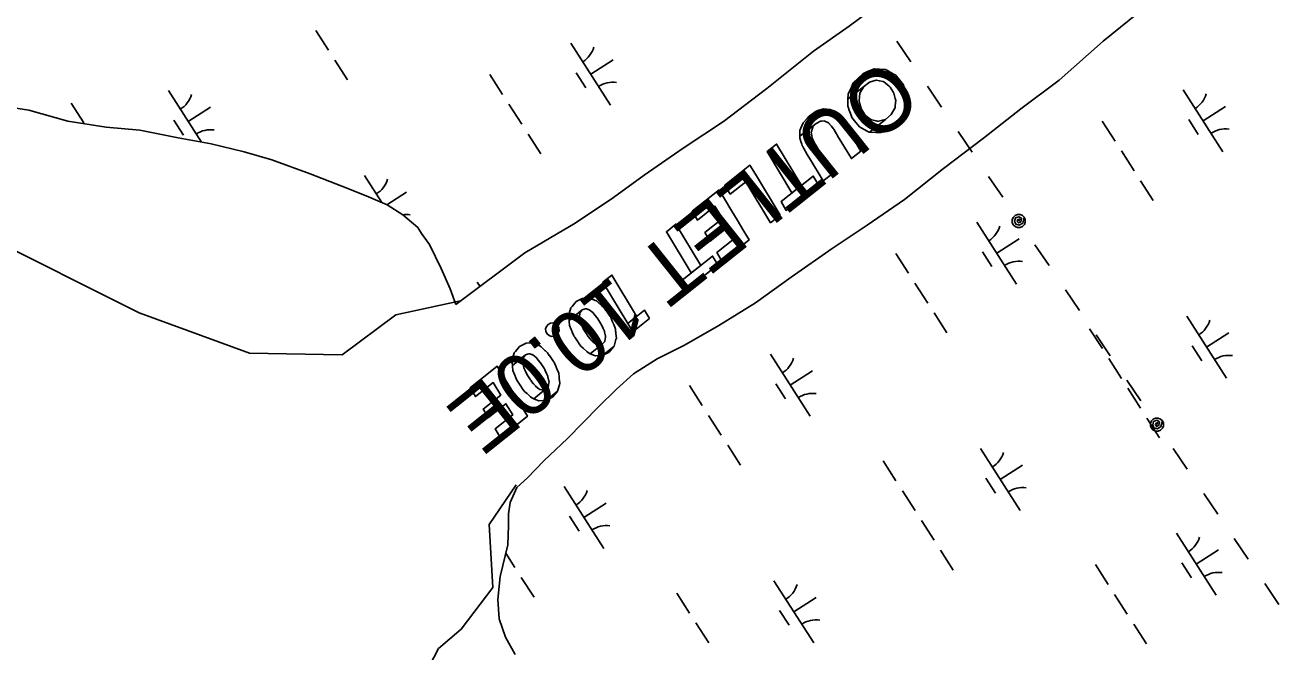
# Model space of a CAD drawing. Extents: x 3962991 to 3983549, y 181631 to 204078.
# Drawn here: x 3970044 to 3970895, y 197689 to 198115 of the extents above; entities that cross this region are included whole.
import ezdxf

# ---------------------------------------------------------------- set-up
doc = ezdxf.new("R2010")
doc.units = 0
for name, color, linetype in [('V-ANNO-MASK', 7, 'Continuous'), ('V-ANNO-MASK2', 7, 'Continuous'), ('V-RIVR-EDGE', 7, 'Continuous'), ('V-RIVR-IDEN', 7, 'Continuous'), ('V-UTIL-LINE', 7, 'Continuous'), ('V-WETL-SWMP', 7, 'Continuous')]:
    doc.layers.add(name, color=color, linetype=linetype)

msp = doc.modelspace()

# ---------------------------------------------------------------- linework, layer by layer
at = {"layer": 'V-ANNO-MASK2'}
for points in [[(3970615.3, 198082.74), (3970612.45, 198081.53), (3970605.99, 198075.33), (3970604.72, 198072.5), (3970602.58, 198067.74), (3970602.44, 198064.29), (3970612.94, 198072.65), (3970616.98, 198075.8), (3970621.62, 198077.12), (3970621.74, 198077.1), (3970623.79, 198076.73), (3970623.79, 198076.73), (3970626.39, 198076.27), (3970626.7, 198076.04), (3970627.97, 198075.06), (3970630.39, 198073.2), (3970630.55, 198072.96), (3970630.56, 198072.96), (3970630.95, 198072.36), (3970633.38, 198068.7), (3970633.39, 198068.71), (3970633.42, 198068.64), (3970633.5, 198068.36), (3970634.49, 198064.66), (3970634.83, 198063.4), (3970634.83, 198063.36), (3970634.49, 198059.88), (3970634.34, 198058.27), (3970634.33, 198058.2), (3970631.84, 198053.81), (3970631.83, 198053.78), (3970627.84, 198050.58), (3970616.92, 198041.89), (3970621.43, 198041.7), (3970624.67, 198041.56), (3970629.85, 198043.76), (3970632.17, 198044.75), (3970632.17, 198044.75), (3970638.43, 198050.6), (3970639.94, 198053.72), (3970642.08, 198058.14), (3970642.28, 198062.07), (3970642.28, 198062.11), (3970642.28, 198062.12), (3970642.41, 198064.63), (3970642.41, 198064.7), (3970642.49, 198066.24), (3970641.66, 198068.8), (3970641.66, 198068.83), (3970641.26, 198070.04), (3970640.1, 198073.61), (3970640.02, 198073.88), (3970639.99, 198073.96), (3970637.3, 198077.41), (3970636.86, 198077.98), (3970636.67, 198078.2), (3970634.85, 198080.54), (3970633.38, 198081.36), (3970633.03, 198081.55), (3970631.16, 198082.6), (3970629.68, 198083.42), (3970629.6, 198083.47), (3970627.84, 198084.44), (3970627.76, 198084.45), (3970623.81, 198084.64), (3970620.19, 198084.81)], [(3970612.88, 198072.53), (3970612.94, 198072.65), (3970602.44, 198064.29), (3970602.43, 198064.22), (3970602.44, 198064.23), (3970602.34, 198061.77), (3970602.33, 198061.65), (3970602.33, 198061.65), (3970602.24, 198059.58), (3970602.96, 198057.61), (3970603.09, 198057.24), (3970603.09, 198057.25), (3970603.65, 198055.7), (3970604.71, 198052.76), (3970604.81, 198052.47), (3970605.07, 198051.76), (3970607.85, 198048.38), (3970607.9, 198048.32), (3970608.07, 198048.12), (3970610.31, 198045.4), (3970611.45, 198044.79), (3970611.48, 198044.78), (3970613.9, 198043.48), (3970615.01, 198042.89), (3970615.06, 198042.86), (3970616.86, 198041.89), (3970616.89, 198041.89), (3970616.92, 198041.89), (3970627.84, 198050.58), (3970627.78, 198050.56), (3970627.75, 198050.55), (3970623.07, 198049.24), (3970622.95, 198049.2), (3970621.48, 198049.52), (3970618.3, 198050.2), (3970618.28, 198050.22), (3970617.29, 198050.96), (3970614.39, 198053.15), (3970614.24, 198053.37), (3970614.2, 198053.43), (3970611.77, 198057.1), (3970611.38, 198057.69), (3970611.29, 198058), (3970610.44, 198061.11), (3970609.99, 198062.74), (3970610.04, 198063.25), (3970610.26, 198065.96), (3970610.44, 198068.1), (3970610.55, 198068.31)], [(3970580.82, 198056.06), (3970576.1, 198052.74), (3970574.66, 198051.16), (3970571.94, 198048.17), (3970571.11, 198046.14), (3970569.8, 198042.95), (3970569.79, 198041), (3970569.77, 198039.05), (3970580.84, 198047.86), (3970583.71, 198049.43), (3970583.75, 198049.43), (3970584.47, 198049.45), (3970586.67, 198049.51), (3970586.79, 198049.46), (3970586.82, 198049.43), (3970589.26, 198048.18), (3970589.8, 198047.58), (3970589.96, 198047.41), (3970590.36, 198046.96), (3970591.35, 198045.85), (3970592.36, 198044.39), (3970592.74, 198043.83), (3970593.19, 198043.16), (3970593.26, 198043.06), (3970594.59, 198040.83), (3970595.4, 198039.48), (3970604.74, 198023.93), (3970611.18, 198029.06), (3970601.84, 198044.6), (3970601.01, 198045.94), (3970599.64, 198048.14), (3970599.58, 198048.25), (3970599.15, 198048.94), (3970598.77, 198049.49), (3970597.77, 198050.96), (3970596.93, 198052.19), (3970596.52, 198052.63), (3970596.35, 198052.79), (3970595.79, 198053.39), (3970594.05, 198055.19), (3970594.02, 198055.21), (3970593.91, 198055.28), (3970592.66, 198055.97), (3970592.25, 198056.2), (3970592.22, 198056.21), (3970591.69, 198056.5), (3970590.25, 198057.29), (3970588.11, 198057.52), (3970585.71, 198057.76), (3970582.67, 198056.71)], [(3970578.65, 198045.4), (3970580.84, 198047.86), (3970569.77, 198039.05), (3970569.76, 198038.33), (3970569.76, 198038.3), (3970569.75, 198037.74), (3970570.2, 198036.4), (3970570.24, 198036.28), (3970570.25, 198036.24), (3970571.09, 198033.72), (3970571.36, 198032.9), (3970571.43, 198032.66), (3970571.74, 198032.14), (3970572.48, 198030.82), (3970572.48, 198030.83), (3970573.36, 198029.27), (3970573.7, 198028.68), (3970574.1, 198027.97), (3970574.16, 198027.85), (3970575.49, 198025.63), (3970576.31, 198024.28), (3970585.65, 198008.73), (3970592.05, 198013.82), (3970582.74, 198029.4), (3970581.93, 198030.76), (3970580.61, 198032.99), (3970580.55, 198033.1), (3970580.14, 198033.8), (3970579.79, 198034.39), (3970579.03, 198036.04), (3970578.38, 198037.43), (3970578.13, 198037.99), (3970578.02, 198038.2), (3970577.91, 198039.15), (3970577.56, 198042.06), (3970577.55, 198042.1), (3970577.61, 198042.3), (3970578.32, 198044.55), (3970578.55, 198045.29)], [(3970570.84, 198005.74), (3970553.97, 198033.78), (3970547.53, 198028.65), (3970564.4, 198000.61)], [(3970539.59, 198013.38), (3970535.95, 198019.43), (3970518.87, 198005.84), (3970522.51, 197999.79), (3970533.16, 198008.26), (3970549.96, 197980.32), (3970556.39, 197985.44)], [(3970582.39, 198006.13), (3970578.82, 198012.09), (3970556.99, 197994.71), (3970560.56, 197988.76)], [(3970518.55, 197996.7), (3970514.94, 198002.71), (3970496.66, 197988.15), (3970500.27, 197982.14), (3970512.18, 197991.63), (3970517.28, 197983.15), (3970505.37, 197973.67), (3970508.9, 197967.8), (3970520.81, 197977.28), (3970525.4, 197969.64), (3970513.49, 197960.16), (3970517.1, 197954.16), (3970535.38, 197968.71), (3970531.77, 197974.71), (3970527.18, 197982.35), (3970523.65, 197988.22)], [(3970502.58, 197951.4), (3970485.71, 197979.44), (3970479.27, 197974.31), (3970496.14, 197946.28)], [(3970514.13, 197951.8), (3970510.56, 197957.75), (3970488.73, 197940.38), (3970492.3, 197934.42)], [(3970459.03, 197916.89), (3970442.24, 197944.83), (3970436.18, 197940.01), (3970452.98, 197912.07)], [(3970422.03, 197929.02), (3970417.97, 197926.83), (3970415.2, 197923.59), (3970414.41, 197922.67), (3970413.29, 197918.68), (3970412.84, 197917.09), (3970413.15, 197914.02), (3970422.12, 197921.16), (3970423.47, 197921.65), (3970424.33, 197921.96), (3970424.94, 197921.82), (3970424.94, 197921.83), (3970426.2, 197921.54), (3970426.59, 197921.45), (3970426.88, 197921.23), (3970429.25, 197919.4), (3970429.48, 197919.11), (3970430.66, 197917.68), (3970430.67, 197917.68), (3970432.03, 197916), (3970432.17, 197915.8), (3970432.62, 197915.09), (3970432.63, 197915.09), (3970434.81, 197911.69), (3970435.05, 197911.2), (3970435.38, 197910.5), (3970436.25, 197908.66), (3970437.13, 197906.78), (3970437.25, 197906.25), (3970437.85, 197903.47), (3970437.98, 197902.86), (3970437.68, 197901.04), (3970437.55, 197900.24), (3970437.48, 197899.84), (3970435.9, 197898.08), (3970427.57, 197891.45), (3970430.49, 197890.23), (3970431.14, 197889.95), (3970435.8, 197890.17), (3970443.72, 197896.48), (3970445.01, 197900.99), (3970445.3, 197902.02), (3970444.95, 197905.28), (3970444.9, 197905.75), (3970444.87, 197906.06), (3970444.8, 197906.71), (3970444.64, 197908.16), (3970444.57, 197908.82), (3970443.54, 197911.26), (3970443.34, 197911.73), (3970442.53, 197913.65), (3970441.73, 197915.55), (3970441.42, 197916.27), (3970441.11, 197916.71), (3970438.8, 197920), (3970438.31, 197920.69), (3970438.17, 197920.89), (3970436.92, 197922.66), (3970435.52, 197923.92), (3970435.24, 197924.17), (3970433.04, 197926.13), (3970432.78, 197926.37), (3970432.53, 197926.58), (3970431.77, 197927.26), (3970431.26, 197927.48), (3970430.96, 197927.61), (3970430.47, 197927.8), (3970427.72, 197928.93), (3970426.69, 197929.35), (3970422.43, 197929.05)], [(3970420.63, 197919.38), (3970422.12, 197921.16), (3970413.16, 197914.02), (3970413.21, 197913.48), (3970413.24, 197913.13), (3970413.3, 197912.56), (3970413.42, 197911.37), (3970413.43, 197911.37), (3970413.46, 197910.99), (3970413.5, 197910.57), (3970414.66, 197907.79), (3970414.81, 197907.43), (3970415.55, 197905.65), (3970416.42, 197903.57), (3970416.51, 197903.34), (3970417, 197902.65), (3970419.29, 197899.33), (3970419.59, 197898.89), (3970420.02, 197898.27), (3970421.15, 197896.63), (3970422.66, 197895.27), (3970423.03, 197894.93), (3970424.94, 197893.2), (3970425.37, 197892.82), (3970426.29, 197891.97), (3970426.87, 197891.74), (3970427.15, 197891.62), (3970427.57, 197891.45), (3970435.9, 197898.08), (3970434.73, 197897.66), (3970433.94, 197897.36), (3970433.23, 197897.5), (3970431.64, 197897.82), (3970431.18, 197898.16), (3970429.06, 197899.73), (3970428.75, 197900.11), (3970427.45, 197901.65), (3970426.18, 197903.17), (3970425.76, 197903.8), (3970425.46, 197904.25), (3970423.22, 197907.6), (3970422.85, 197908.38), (3970422.74, 197908.61), (3970421.79, 197910.61), (3970420.97, 197912.33), (3970420.89, 197912.74), (3970420.24, 197915.94), (3970420.17, 197916.33), (3970420.09, 197916.68), (3970420.4, 197918.21), (3970420.54, 197918.94)], [(3970467.77, 197915.38), (3970464.33, 197921.1), (3970452.98, 197912.07), (3970456.42, 197906.34)], [(3970400.6, 197912.23), (3970399, 197911.39), (3970397.83, 197910.02), (3970397.3, 197908.3), (3970397.45, 197906.53), (3970398.27, 197904.94), (3970399.64, 197903.77), (3970401.34, 197903.23), (3970403.11, 197903.39), (3970404.72, 197904.22), (3970405.88, 197905.6), (3970406.44, 197907.29), (3970406.29, 197909.06), (3970405.47, 197910.67), (3970404.1, 197911.82), (3970402.4, 197912.36)], [(3970383.64, 197898.47), (3970379.58, 197896.27), (3970376.81, 197893.03), (3970376.03, 197892.11), (3970374.9, 197888.13), (3970374.45, 197886.53), (3970374.76, 197883.46), (3970383.74, 197890.6), (3970385.09, 197891.09), (3970385.95, 197891.4), (3970386.55, 197891.27), (3970386.56, 197891.27), (3970387.81, 197890.98), (3970388.21, 197890.89), (3970388.5, 197890.67), (3970390.86, 197888.84), (3970391.1, 197888.56), (3970392.28, 197887.12), (3970392.28, 197887.12), (3970393.65, 197885.45), (3970393.78, 197885.25), (3970394.24, 197884.53), (3970394.24, 197884.54), (3970396.43, 197881.14), (3970396.67, 197880.64), (3970396.99, 197879.94), (3970397.86, 197878.1), (3970398.74, 197876.23), (3970398.86, 197875.69), (3970399.46, 197872.91), (3970399.59, 197872.3), (3970399.29, 197870.49), (3970399.16, 197869.68), (3970399.09, 197869.29), (3970397.52, 197867.53), (3970389.18, 197860.89), (3970392.1, 197859.67), (3970392.75, 197859.39), (3970397.41, 197859.62), (3970405.33, 197865.92), (3970406.62, 197870.43), (3970406.91, 197871.46), (3970406.56, 197874.73), (3970406.51, 197875.19), (3970406.48, 197875.51), (3970406.41, 197876.15), (3970406.26, 197877.61), (3970406.18, 197878.26), (3970405.15, 197880.7), (3970404.96, 197881.17), (3970404.14, 197883.1), (3970403.34, 197885), (3970403.03, 197885.71), (3970402.73, 197886.15), (3970400.41, 197889.45), (3970399.92, 197890.13), (3970399.79, 197890.33), (3970398.53, 197892.1), (3970397.13, 197893.36), (3970396.85, 197893.61), (3970394.66, 197895.57), (3970394.39, 197895.81), (3970394.15, 197896.03), (3970393.39, 197896.71), (3970392.88, 197896.92), (3970392.57, 197897.05), (3970392.08, 197897.25), (3970389.33, 197898.38), (3970388.31, 197898.8), (3970384.05, 197898.5)], [(3970443.4, 197896.11), (3970443.71, 197896.47), (3970435.8, 197890.17), (3970435.95, 197890.18), (3970440.32, 197892.56)], [(3970382.24, 197888.83), (3970383.74, 197890.6), (3970374.77, 197883.47), (3970374.82, 197882.92), (3970374.86, 197882.58), (3970374.92, 197882), (3970375.03, 197880.81), (3970375.04, 197880.82), (3970375.07, 197880.44), (3970375.12, 197880.02), (3970376.28, 197877.23), (3970376.43, 197876.88), (3970377.16, 197875.09), (3970378.03, 197873.01), (3970378.13, 197872.78), (3970378.61, 197872.09), (3970380.9, 197868.78), (3970381.2, 197868.33), (3970381.63, 197867.71), (3970382.76, 197866.08), (3970384.27, 197864.71), (3970384.65, 197864.37), (3970386.56, 197862.64), (3970386.98, 197862.26), (3970387.9, 197861.42), (3970388.48, 197861.18), (3970388.76, 197861.06), (3970389.18, 197860.89), (3970397.52, 197867.53), (3970396.35, 197867.1), (3970395.55, 197866.81), (3970394.85, 197866.95), (3970393.26, 197867.26), (3970392.79, 197867.61), (3970390.68, 197869.17), (3970390.36, 197869.56), (3970389.07, 197871.1), (3970387.79, 197872.62), (3970387.37, 197873.24), (3970387.07, 197873.69), (3970384.83, 197877.05), (3970384.46, 197877.83), (3970384.36, 197878.05), (3970383.4, 197880.06), (3970382.58, 197881.78), (3970382.5, 197882.18), (3970381.86, 197885.38), (3970381.78, 197885.78), (3970381.71, 197886.12), (3970382.01, 197887.65), (3970382.15, 197888.38)], [(3970368.09, 197876.93), (3970364.48, 197882.94), (3970346.2, 197868.38), (3970349.81, 197862.38), (3970361.72, 197871.86), (3970366.82, 197863.38), (3970354.91, 197853.9), (3970358.44, 197848.04), (3970370.35, 197857.52), (3970374.94, 197849.87), (3970363.03, 197840.39), (3970366.64, 197834.39), (3970384.92, 197848.94), (3970381.32, 197854.94), (3970376.72, 197862.58), (3970373.2, 197868.45)], [(3970405.01, 197865.55), (3970405.32, 197865.92), (3970397.41, 197859.62), (3970397.56, 197859.62), (3970401.94, 197862)]]:
    msp.add_lwpolyline(points, close=True, dxfattribs=at)
at = {"layer": 'V-RIVR-EDGE'}
for points in [[(3969206.8, 198682.32), (3969252.51, 198629.16), (3969448.4, 198415.46), (3969628.85, 198224.32), (3969670.41, 198192.26), (3969837.8, 198074.73), (3969909.03, 198027.24), (3970014.7, 197972.63), (3970121.55, 197919.21), (3970196.34, 197891.9), (3970259.26, 197890.71), (3970295.75, 197917.75), (3970339.58, 197927.32)], [(3970377.34, 197802.49), (3970358.99, 197775.55), (3970361.36, 197732.81), (3970339.99, 197704.32), (3970324.56, 197691.26), (3970309.13, 197661.58)]]:
    msp.add_lwpolyline(points, dxfattribs=at)
at = {"layer": 'V-UTIL-LINE'}
for points in [[(3970635.57, 198103.65), (3970645.11, 198089.58)], [(3970656.34, 198073.03), (3970665.87, 198058.96)], [(3970677.1, 198042.4), (3970686.64, 198028.33)], [(3970697.86, 198011.78), (3970707.4, 197997.71)], [(3970718.33, 197981.56), (3970718.85, 197982.9), (3970717.72, 197982.62), (3970717.26, 197981.33), (3970718.21, 197980.22), (3970719.66, 197981.1), (3970720.16, 197983.39), (3970718.33, 197984.5), (3970716.03, 197983.72), (3970715.49, 197981.49), (3970716.31, 197979.42), (3970718.62, 197978.74), (3970720.99, 197980.15), (3970722.06, 197984.08), (3970720.81, 197985.32), (3970719.18, 197985.98), (3970717.42, 197985.96), (3970715.81, 197985.28), (3970714.57, 197984.03), (3970713.91, 197982.41), (3970713.92, 197980.65), (3970714.61, 197979.03), (3970715.86, 197977.8), (3970717.48, 197977.14), (3970719.24, 197977.15), (3970720.86, 197977.83), (3970722.09, 197979.08), (3970722.75, 197980.71), (3970722.74, 197982.47), (3970722.06, 197984.08)], [(3970729.28, 197965.43), (3970738.82, 197951.35)], [(3970750.05, 197934.8), (3970759.58, 197920.73)], [(3970770.81, 197904.18), (3970780.35, 197890.1)], [(3970791.57, 197873.55), (3970801.11, 197859.48)], [(3970812.04, 197843.33), (3970812.56, 197844.67), (3970811.43, 197844.39), (3970810.97, 197843.1), (3970811.92, 197841.99), (3970813.37, 197842.87), (3970813.87, 197845.16), (3970812.05, 197846.27), (3970809.74, 197845.49), (3970809.2, 197843.27), (3970810.02, 197841.19), (3970812.34, 197840.51), (3970814.7, 197841.92), (3970815.77, 197845.85), (3970814.52, 197847.09), (3970812.89, 197847.75), (3970811.14, 197847.74), (3970809.52, 197847.05), (3970808.29, 197845.8), (3970807.62, 197844.18), (3970807.64, 197842.42), (3970808.32, 197840.8), (3970809.57, 197839.57), (3970811.2, 197838.91), (3970812.95, 197838.92), (3970814.57, 197839.61), (3970815.8, 197840.85), (3970816.46, 197842.48), (3970816.45, 197844.24), (3970815.77, 197845.85)], [(3970822.99, 197827.2), (3970832.53, 197813.13)], [(3970843.76, 197796.57), (3970853.3, 197782.5)], [(3970864.52, 197765.95), (3970874.06, 197751.88)], [(3970885.28, 197735.32), (3970894.82, 197721.25)]]:
    msp.add_lwpolyline(points, dxfattribs=at)
at = {"layer": 'V-WETL-SWMP'}
for p, q in [((3970603.28, 198113.84), (3970625.21, 198130.17)), ((3970775.68, 198103.63), (3970809.68, 198131.38)), ((3970241.36, 198110.98), (3970250, 198097.51)), ((3970579.02, 198096.87), (3970603.28, 198113.84)), ((3970414.36, 198102.32), (3970441.35, 198060.23)), ((3970745.76, 198077.15), (3970775.68, 198103.63)), ((3970254.31, 198090.77), (3970262.95, 198077.31)), ((3970427.85, 198081.27), (3970443.01, 198090.99)), ((3970547.31, 198071.52), (3970579.02, 198096.87)), ((3970418.12, 198082.16), (3970424.6, 198072.06)), ((3970359.46, 198081.02), (3970368.09, 198067.55)), ((3970719.79, 198057.8), (3970745.76, 198077.15)), ((3970141.3, 198070.09), (3970163.75, 198035.08)), ((3970517.88, 198049.16), (3970547.31, 198071.52)), ((3970829.87, 198070.6), (3970856.85, 198028.51)), ((3970013.12, 198062.02), (3970046.66, 198056.9)), ((3970046.66, 198056.9), (3970073.22, 198049.28)), ((3970075.42, 198061.61), (3970084.06, 198048.15)), ((3970154.8, 198049.04), (3970169.95, 198058.76)), ((3970372.41, 198060.82), (3970381.04, 198047.35)), ((3970694.42, 198037.87), (3970719.79, 198057.8)), ((3970843.36, 198049.55), (3970858.51, 198059.27)), ((3970073.22, 198049.28), (3970099.12, 198045.17)), ((3970145.06, 198049.93), (3970151.54, 198039.83)), ((3970490.71, 198030.96), (3970517.88, 198049.16)), ((3970774.96, 198049.3), (3970783.6, 198035.83)), ((3970833.62, 198050.44), (3970840.1, 198040.34)), ((3970099.12, 198045.17), (3970122.03, 198043.33)), ((3970122.03, 198043.33), (3970147.96, 198038.04)), ((3970385.36, 198040.61), (3970394, 198027.15)), ((3970147.96, 198038.04), (3970170.33, 198033.85)), ((3970170.33, 198033.85), (3970192.74, 198028.48)), ((3970464.13, 198012.76), (3970490.71, 198030.96)), ((3970667.3, 198017.32), (3970694.42, 198037.87)), ((3970192.74, 198028.48), (3970211.63, 198023.03)), ((3970211.63, 198023.03), (3970237.64, 198013.64)), ((3970787.91, 198029.1), (3970796.55, 198015.63)), ((3970237.64, 198013.64), (3970258.94, 198005.32)), ((3970640.78, 197996.2), (3970667.3, 198017.32)), ((3970258.94, 198005.32), (3970275.51, 197998.65)), ((3970274.33, 198012.55), (3970286.2, 197994.04)), ((3970443.34, 197997.63), (3970464.13, 198012.76)), ((3970800.87, 198008.9), (3970809.5, 197995.43)), ((3970275.51, 197998.65), (3970289.72, 197992.51)), ((3970289.53, 197992.6), (3970302.97, 198001.22)), ((3970417.33, 197980.04), (3970443.34, 197997.63)), ((3970289.72, 197992.51), (3970300.43, 197985.71)), ((3970615.35, 197978.62), (3970640.78, 197996.2)), ((3970300.43, 197985.71), (3970310.59, 197977.14)), ((3970383.16, 197959.92), (3970417.33, 197980.04)), ((3970689.83, 197980.83), (3970716.82, 197938.74)), ((3970310.59, 197977.14), (3970313.03, 197973.09)), ((3970313.03, 197973.09), (3970318.47, 197965.59)), ((3970591.65, 197962.84), (3970615.35, 197978.62)), ((3970318.47, 197965.59), (3970326.46, 197949.34)), ((3970563.92, 197943.45), (3970591.65, 197962.84)), ((3970703.33, 197959.78), (3970718.48, 197969.5)), ((3970336.39, 197924.93), (3970383.16, 197959.92)), ((3970634.93, 197959.53), (3970643.56, 197946.06)), ((3970693.59, 197960.67), (3970700.07, 197950.57)), ((3970326.46, 197949.34), (3970332.63, 197935.4)), ((3970350.9, 197940.12), (3970352.78, 197937.19)), ((3970539.66, 197925.89), (3970563.92, 197943.45)), ((3970647.88, 197939.33), (3970656.52, 197925.86)), ((3970332.63, 197935.4), (3970336.39, 197924.93)), ((3970514.77, 197910.67), (3970539.66, 197925.89)), ((3970660.83, 197919.12), (3970669.47, 197905.65)), ((3970832.28, 197916.88), (3970859.27, 197874.78)), ((3970491.6, 197897.25), (3970514.77, 197910.67)), ((3970766.4, 197908.4), (3970775.04, 197894.93)), ((3970845.78, 197895.83), (3970860.93, 197905.55)), ((3970473.03, 197888.03), (3970491.6, 197897.25)), ((3970836.04, 197896.72), (3970842.52, 197886.62)), ((3970456.83, 197877.7), (3970473.03, 197888.03)), ((3970549.8, 197891.05), (3970576.79, 197848.96)), ((3970779.36, 197888.2), (3970787.99, 197874.73)), ((3970445.33, 197867.47), (3970456.83, 197877.7)), ((3970563.29, 197870.01), (3970578.45, 197879.72)), ((3970494.9, 197869.76), (3970503.53, 197856.29)), ((3970553.56, 197870.89), (3970560.04, 197860.79)), ((3970433.27, 197855.47), (3970445.33, 197867.47)), ((3970792.31, 197867.99), (3970800.94, 197854.52)), ((3970412.04, 197833.87), (3970433.27, 197855.47)), ((3970507.85, 197849.55), (3970516.49, 197836.08)), ((3970805.26, 197847.79), (3970813.9, 197834.32)), ((3970396.09, 197818.76), (3970412.04, 197833.87)), ((3970520.8, 197829.35), (3970529.44, 197815.88)), ((3970692.25, 197827.1), (3970719.24, 197785.01)), ((3970384.88, 197807.28), (3970396.09, 197818.76)), ((3970626.37, 197818.63), (3970635.01, 197805.16)), ((3970705.74, 197806.06), (3970720.9, 197815.77)), ((3970377.79, 197800.63), (3970384.88, 197807.28)), ((3970409.77, 197801.28), (3970436.76, 197759.19)), ((3970696.01, 197806.94), (3970702.49, 197796.84)), ((3970373.13, 197790.42), (3970377.79, 197800.63)), ((3970639.32, 197798.42), (3970647.96, 197784.95)), ((3970372.03, 197782.65), (3970373.13, 197790.42)), ((3970423.26, 197780.23), (3970438.42, 197789.95)), ((3970372.12, 197774.88), (3970372.03, 197782.65)), ((3970413.53, 197781.12), (3970420.01, 197771.02)), ((3970652.28, 197778.22), (3970660.91, 197764.75)), ((3970371.68, 197761.74), (3970372.12, 197774.88)), ((3970825.28, 197769.56), (3970852.26, 197727.47)), ((3970366.55, 197740.18), (3970371.68, 197761.74)), ((3970370.29, 197755.92), (3970376.45, 197746.31)), ((3970665.23, 197758.02), (3970673.86, 197744.55)), ((3970838.77, 197748.51), (3970853.92, 197758.23)), ((3970770.37, 197748.26), (3970779.01, 197734.79)), ((3970829.03, 197749.4), (3970835.51, 197739.3)), ((3970364.94, 197724.64), (3970366.55, 197740.18)), ((3970380.77, 197739.58), (3970389.41, 197726.11)), ((3970552.22, 197737.33), (3970579.2, 197695.24)), ((3970365.69, 197711.51), (3970364.94, 197724.64)), ((3970486.34, 197728.86), (3970494.97, 197715.39)), ((3970565.71, 197716.28), (3970580.87, 197726)), ((3970783.32, 197728.06), (3970791.96, 197714.59)), ((3970555.98, 197717.17), (3970562.45, 197707.07)), ((3970370.02, 197699.02), (3970365.69, 197711.51)), ((3970499.29, 197708.65), (3970507.93, 197695.18)), ((3970796.28, 197707.86), (3970804.91, 197694.39)), ((3970376.73, 197687.15), (3970370.02, 197699.02))]:
    msp.add_line(p, q, dxfattribs=at)
for centre, start, end in [((3970413.15, 198104.66), 301.89187, 343.43553), ((3970442.96, 198058.15), 81.89186, 123.43552), ((3970140.09, 198072.42), 301.89187, 343.43553), ((3970828.65, 198072.94), 301.89187, 343.43553), ((3970169.9, 198025.92), 81.89186, 123.43552), ((3970858.47, 198026.43), 81.89186, 123.43552), ((3970273.11, 198014.88), 301.89187, 343.43553), ((3970302.93, 197968.38), 81.89186, 98.60087), ((3970688.62, 197983.16), 301.89187, 343.43553), ((3970718.43, 197936.66), 81.89186, 123.43552), ((3970831.07, 197919.21), 301.89187, 343.43553), ((3970548.59, 197893.39), 301.89187, 343.43553), ((3970860.88, 197872.71), 81.89186, 123.43552), ((3970578.4, 197846.88), 81.89186, 123.43552), ((3970691.04, 197829.44), 301.89187, 343.43553), ((3970408.56, 197803.62), 301.89187, 343.43553), ((3970720.85, 197782.93), 81.89186, 123.43552), ((3970438.37, 197757.11), 81.89186, 123.43552), ((3970824.06, 197771.9), 301.89187, 343.43553), ((3970853.88, 197725.39), 81.89186, 123.43552), ((3970551, 197739.66), 301.89187, 343.43553), ((3970580.82, 197693.16), 81.89186, 123.43552)]:
    msp.add_arc(centre, 17.62, start, end, dxfattribs=at)

# ---------------------------------------------------------------- texts
at = {"layer": 'V-ANNO-MASK'}
msp.add_text('OUTLET 10.0E', height=41.9999, rotation=218.52087, dxfattribs=at).set_placement((3970628.45, 198093.07))
at = {"layer": 'V-RIVR-IDEN'}
msp.add_text('OUTLET 10.0E', height=41.9999, rotation=218.52087, dxfattribs=at).set_placement((3970628.45, 198093.07))

doc.saveas('drawing.dxf')
